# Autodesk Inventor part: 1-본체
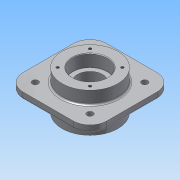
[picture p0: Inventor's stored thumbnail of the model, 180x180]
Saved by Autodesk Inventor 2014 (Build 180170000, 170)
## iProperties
Created: 2015-09
Part Number: 1-본체
Material: 알루미늄 6061
Document SubType Name: Modeling
Designer: study
Density: 2.70916 g/cm^3
Appearance: 알루미늄 - 평지
Mass: 1467 g
Surface Area: 792.775 cm^2
Volume: 541.496 cm^3
Author: study
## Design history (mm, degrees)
sketch "스케치1"
  geometry: L1 (-75, 75)-(75, 75); L2 (75, 75)-(75, -75); L3 (75, -75)-(-75, -75); L4 (-75, -75)-(-75, 75); L5 (-75, 75)-(75, -75); L6 (75, 75)-(-75, -75); 1 further point
  constraints: 12 end point, 2 midpoint, 2 parallel, 1 horizontal, 1 perpendicular
  dimensions: "d0" = 150 distance of L2.end L3.end; "d1" = 150 distance of L1.end L2.end
extrude "돌출1" new body sketch "스케치1" stored distance "d2" = 12; taper "d3" = 0 deg
sketch "스케치2"
  geometry: C1 r 50 at (0, 0); 1 further point
  constraints: 1 centre point, 1 coincident
  dimensions: "d4" = 100 diameter of C1
extrude "돌출2" join sketch "스케치2" distance "d5" = 23; taper "d6" = 0 deg
sketch "스케치3"
  geometry: C1 r 50 at (0, 0) reference; 1 further point
extrude "돌출3" join sketch "스케치3" distance "d7" = 35; taper "d8" = 0 deg
hole "구멍1" diameter "d11" = 45; stored, may be unused: countersink angle "d15" = 90 deg, drill point angle "d17" = 118 deg; dims "d9" = 10, "d10" = 10, "d12" = 6, "d13" = 62, "d14" = 22, "d16" = 8
hole "구멍2" diameter "d20" = 45; stored, may be unused: countersink angle "d24" = 90 deg, drill point angle "d26" = 118 deg; dims "d18" = 10, "d19" = 10, "d21" = 6, "d22" = 62, "d23" = 22, "d25" = 8
sketch "스케치4"
  geometry: L1 (-49, 49)-(49, 49); L2 (49, 49)-(49, -49); L3 (49, -49)-(-49, -49); L4 (-49, -49)-(-49, 49); L5 (-49, 49)-(49, -49); L6 (49, 49)-(-49, -49); C1 r 50 at (0, 0) reference; C2 r 10 at (-49, 49); C3 r 10 at (49, 49); C4 r 10 at (49, -49); C5 r 10 at (-49, -49)
  constraints: 12 end point, 4 centre point, 4 coincident, 3 equal radius, 2 midpoint, 2 parallel, 1 horizontal, 1 perpendicular
  dimensions: "d27" = 98 distance of L1.start L1.end; "d28" = 98 distance of L1.end L2.end; "d29" = 20 diameter of C2
extrude "돌출4" join sketch "스케치4" distance "d30" = 5; taper "d31" = 0 deg
sketch "스케치5" dims "d32" = 82
  geometry: L1 (0, 0)-(-72.601, 0); L2 (0, 0)-(-35.355, 35.355); 2 further points
  constraints: 4 end point, 1 coincident, 1 horizontal, 1 point on line, 5 other
  dimensions: "d33" = 45 deg angle of L1 L2
hole "구멍3" sketch "스케치5" at (-28.991, 28.991) diameter "d34" = 4.917; stored, may be unused: countersink angle "d38" = 90 deg, drill point angle "d40" = 118 deg; dims "d35" = 10, "d36" = 62, "d37" = 22, "d39" = 13
sketch "스케치6"
  geometry: C1 r 10 at (0, 0) reference; C2 r 10 at (98, 0) reference; C3 r 10 at (98, -98) reference; C4 r 10 at (0, -98) reference; 5 further points
  constraints: 4 coincident
hole "구멍4" sketch "스케치6" at (0, 0), (98, 0), (98, -98), (0, -98) diameter "d44" = 11; stored, may be unused: countersink angle "d48" = 90 deg, drill point angle "d50" = 118 deg; dims "d45" = 10, "d46" = 62, "d47" = 22, "d49" = 13
sketch "스케치7"
  geometry: C1 r 50 at (0, 0) reference; 1 further point
  constraints: 1 vertical alignment, 1 other
  dimensions: "d51" = 65 distance of C1.centre point (0, 65)
feature "엠보싱1" sketch "스케치7" dims "d52" = 1, "d53" = 0
fillet "모깎기1" dims "d54" = 30
fillet "모깎기2" dims "d55" = 0.3
fillet "모깎기3" dims "d56" = 3
chamfer "모따기1" distance "d57" = 1; stored, may be unused: second distance "d58" = 2, angle "d59" = 45 deg
node "작업 평면1"
node "솔리드1"
pattern_circular "원형 패턴1" dims angle "d42" = 360 deg
mirror "대칭1"
